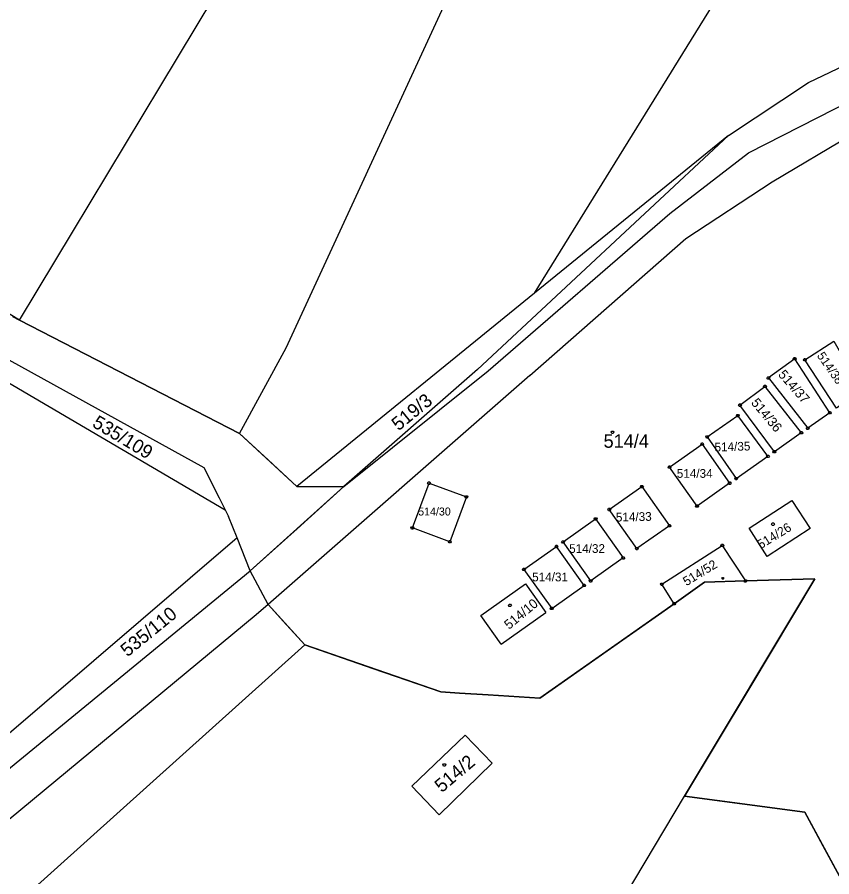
# Model space of a CAD drawing. Extents: x -634640 to -629202, y -1196156 to -1190068.
# Drawn here: x -632066.6 to -631964.4, y -1192921.2 to -1192813.3 of the extents above; entities that cross this region are included whole.
import ezdxf

# ---------------------------------------------------------------- set-up
doc = ezdxf.new("R2010")
doc.units = 0
for name, color, linetype in [('Obvod převzatý', 7, 'Continuous'), ('Obvod šetřený', 7, 'Continuous'), ('Vrstva 1', 7, 'Continuous'), ('Vrstva 2', 7, 'Continuous'), ('Vrstva 3', 7, 'Continuous'), ('Vrstva 5', 7, 'Continuous'), ('Vrstva 8', 7, 'Continuous')]:
    doc.layers.add(name, color=color, linetype=linetype)

msp = doc.modelspace()

# ---------------------------------------------------------------- linework, layer by layer
at = {"layer": 'Obvod převzatý'}
for points in [[(-632038.72, -1192865.56), (-632035.115, -1192868.88), (-632031.51, -1192872.2), (-632025.62, -1192872.23)], [(-632025.62, -1192872.23), (-632031.5, -1192877.515), (-632037.38, -1192882.8)], [(-632035.13, -1192887.03), (-632032.815, -1192889.565), (-632030.5, -1192892.1), (-632021.98, -1192895.05), (-632013.46, -1192898), (-632011.12, -1192898.15), (-632007.49, -1192898.38), (-632004.245, -1192898.59), (-632001, -1192898.8), (-631992.575, -1192892.865), (-631984.15, -1192886.93), (-631980.34, -1192884.24), (-631975.21, -1192884.08), (-631970.855, -1192883.94), (-631966.5, -1192883.8), (-631974.67, -1192897.455), (-631982.84, -1192911.11)]]:
    msp.add_lwpolyline(points, dxfattribs=at)
at = {"layer": 'Obvod šetřený'}
msp.add_line((-632035.13, -1192887.03), (-632037.38, -1192882.8), dxfattribs=at)
for points in [[(-632038.72, -1192865.56), (-632052.53, -1192858.45), (-632066.34, -1192851.34), (-632084.4, -1192840.38), (-632101.57, -1192829.88), (-632120.195, -1192818.495), (-632138.82, -1192807.11), (-632139.83, -1192806.49), (-632148.825, -1192801.24), (-632157.82, -1192795.99), (-632167.43, -1192790.385), (-632177.04, -1192784.78), (-632195.93, -1192773.755), (-632214.82, -1192762.73), (-632233.505, -1192751.82), (-632252.19, -1192740.91), (-632270.795, -1192730.055), (-632289.4, -1192719.2), (-632293.81, -1192716.63), (-632307.91, -1192708.405), (-632322.01, -1192700.18), (-632332.91, -1192693.815), (-632343.81, -1192687.45)], [(-631881.59, -1192883.11), (-631882.955, -1192885.455), (-631884.32, -1192887.8), (-631884.83, -1192886.64), (-631885.34, -1192885.48), (-631901.16, -1192887.14), (-631916.98, -1192888.8), (-631933.245, -1192909.24), (-631949.51, -1192929.68), (-631956.32, -1192925.645), (-631963.13, -1192921.61), (-631965.445, -1192917.355), (-631967.76, -1192913.1), (-631975.3, -1192912.105), (-631982.84, -1192911.11)]]:
    msp.add_lwpolyline(points, dxfattribs=at)
at = {"layer": 'Vrstva 1'}
for p, q in [((-632001.69, -1192847.96), (-631910.15, -1192700.05)), ((-632066.34, -1192851.34), (-631994.7, -1192732.44)), ((-632032.85, -1192854.81), (-631979.98, -1192740.13)), ((-631967.27, -1192821.5), (-631956.23, -1192816.21)), ((-631977.31, -1192828.14), (-631967.27, -1192821.5)), ((-631974.82, -1192830.35), (-631961.8, -1192823.68)), ((-632008.84, -1192857.55), (-631977.31, -1192828.14)), ((-631977.31, -1192828.14), (-632001.69, -1192847.96)), ((-631971.86, -1192833.96), (-631960.48, -1192827.21)), ((-631984.69, -1192837.97), (-631974.82, -1192830.35)), ((-631982.7, -1192841.11), (-631971.86, -1192833.96)), ((-632007.49, -1192857.7), (-631984.69, -1192837.97)), ((-632002.29, -1192858.29), (-631982.7, -1192841.11)), ((-632001.69, -1192847.96), (-632031.51, -1192872.2)), ((-632067.23, -1192850.88), (-632066.34, -1192851.34)), ((-632066.34, -1192851.34), (-632038.72, -1192865.56)), ((-632038.72, -1192865.56), (-632032.85, -1192854.81)), ((-632068.95, -1192855.67), (-632043.18, -1192869.83)), ((-631969.02, -1192856.18), (-631972.32, -1192858.6)), ((-631964.61, -1192862.96), (-631969.02, -1192856.18)), ((-632070.2, -1192857.75), (-632040.51, -1192875.14)), ((-632002.29, -1192858.29), (-632035.13, -1192887.03)), ((-632008.84, -1192857.55), (-632025.62, -1192872.23)), ((-632025.62, -1192872.23), (-632007.49, -1192857.7)), ((-631972.32, -1192858.6), (-631967.38, -1192864.91)), ((-631975.89, -1192862.01), (-631972.75, -1192859.65)), ((-631972.75, -1192859.65), (-631968.19, -1192865.48)), ((-631971.57, -1192867.85), (-631975.89, -1192862.01)), ((-631980, -1192866), (-631976.16, -1192863.32)), ((-631964.61, -1192862.96), (-631967.38, -1192864.91)), ((-632038.72, -1192865.56), (-632031.51, -1192872.2)), ((-631980, -1192866), (-631976.37, -1192871.23)), ((-631968.19, -1192865.48), (-631971.57, -1192867.85)), ((-631980.64, -1192866.9), (-631977.19, -1192871.8)), ((-632043.18, -1192869.83), (-632041.27, -1192873.63)), ((-632037.38, -1192882.8), (-632025.62, -1192872.23)), ((-632031.51, -1192872.2), (-632025.62, -1192872.23)), ((-632017.02, -1192877.42), (-632014.93, -1192871.8)), ((-632014.93, -1192871.8), (-632010.24, -1192873.53)), ((-631977.19, -1192871.8), (-631981.28, -1192874.68)), ((-632010.24, -1192873.53), (-632012.32, -1192879.16)), ((-632041.27, -1192873.63), (-632040.51, -1192875.14)), ((-632040.51, -1192875.14), (-632040.09, -1192875.97)), ((-632039.03, -1192878.65), (-632040.09, -1192875.97)), ((-632012.32, -1192879.16), (-632017.02, -1192877.42)), ((-631984.74, -1192877.14), (-631988.84, -1192880.01)), ((-632039.03, -1192878.65), (-632080.95, -1192914.66)), ((-632037.38, -1192882.8), (-632039.03, -1192878.65)), ((-632003.01, -1192882.62), (-631998.93, -1192879.75)), ((-631995.45, -1192884.64), (-631998.93, -1192879.75)), ((-631985.7, -1192884.5), (-631978.11, -1192879.62)), ((-631978.11, -1192879.62), (-631975.21, -1192884.08)), ((-632079.04, -1192916.97), (-632037.38, -1192882.8)), ((-632003.01, -1192882.62), (-631999.53, -1192887.52)), ((-631980.34, -1192884.24), (-631984.15, -1192886.93)), ((-631982.84, -1192911.11), (-631966.5, -1192883.8)), ((-631975.21, -1192884.08), (-631980.34, -1192884.24)), ((-631966.5, -1192883.8), (-631975.21, -1192884.08)), ((-632008.42, -1192888.41), (-632002.82, -1192884.43)), ((-632002.82, -1192884.43), (-632000.27, -1192888.02)), ((-631999.53, -1192887.52), (-631995.45, -1192884.64)), ((-631984.15, -1192886.93), (-631985.7, -1192884.5)), ((-632035.13, -1192887.03), (-632036.64, -1192888.35)), ((-632030.5, -1192892.1), (-632035.13, -1192887.03)), ((-631984.15, -1192886.93), (-632001, -1192898.8)), ((-632036.64, -1192888.35), (-632075.85, -1192920.82)), ((-632005.87, -1192892), (-632008.42, -1192888.41)), ((-632005.87, -1192892), (-632000.27, -1192888.02)), ((-632030.5, -1192892.1), (-632121.63, -1192973.87)), ((-632013.46, -1192898), (-632030.5, -1192892.1)), ((-632011.12, -1192898.15), (-632013.46, -1192898)), ((-632007.49, -1192898.38), (-632011.12, -1192898.15)), ((-632001, -1192898.8), (-632007.49, -1192898.38)), ((-632017.09, -1192909.84), (-632010.38, -1192903.45)), ((-632010.38, -1192903.45), (-632006.99, -1192906.95)), ((-632006.99, -1192906.95), (-632013.66, -1192913.42)), ((-632013.66, -1192913.42), (-632017.09, -1192909.84)), ((-632058.84, -1193038.11), (-631982.84, -1192911.11)), ((-631982.84, -1192911.11), (-631967.76, -1192913.1)), ((-631967.76, -1192913.1), (-631963.13, -1192921.61))]:
    msp.add_line(p, q, dxfattribs=at)
for points in [[(-631963.79, -1192862.39), (-631967.75, -1192856.31), (-631964.11, -1192853.98), (-631960.58, -1192860.14), (-631963.79, -1192862.39)], [(-631976.37, -1192871.23), (-631972.38, -1192868.43), (-631976.16, -1192863.32)], [(-631981.28, -1192874.68), (-631984.73, -1192869.78), (-631980.64, -1192866.9)], [(-631988.84, -1192880.01), (-631992.3, -1192875.11), (-631988.2, -1192872.24), (-631984.74, -1192877.14)], [(-631974.74, -1192877.44), (-631969.36, -1192873.98), (-631967.07, -1192877.49), (-631972.48, -1192881), (-631974.74, -1192877.44)], [(-631998.1, -1192879.18), (-631994.01, -1192876.29), (-631990.54, -1192881.19)], [(-631990.54, -1192881.19), (-631994.63, -1192884.07), (-631998.1, -1192879.18)]]:
    msp.add_lwpolyline(points, dxfattribs=at)
at = {"layer": 'Vrstva 3'}
for points in [[(-631991.8, -1192865.27), (-631991.71, -1192865.42), (-631991.8, -1192865.57), (-631991.98, -1192865.57), (-631992.07, -1192865.42), (-631991.98, -1192865.27), (-631991.8, -1192865.27)], [(-631977.98, -1192883.65), (-631977.919, -1192883.75), (-631977.98, -1192883.85), (-631978.1, -1192883.85), (-631978.161, -1192883.75), (-631978.1, -1192883.65), (-631977.98, -1192883.65)]]:
    msp.add_lwpolyline(points, dxfattribs=at)
at = {"layer": 'Vrstva 5'}
for points in [[(-631971.65, -1192876.8), (-631971.56, -1192876.95), (-631971.65, -1192877.1), (-631971.83, -1192877.1), (-631971.92, -1192876.95), (-631971.83, -1192876.8), (-631971.65, -1192876.8)], [(-632004.68, -1192886.99), (-632004.59, -1192887.14), (-632004.68, -1192887.29), (-632004.86, -1192887.29), (-632004.95, -1192887.14), (-632004.86, -1192886.99), (-632004.68, -1192886.99)], [(-632012.91, -1192907.03), (-632012.82, -1192907.18), (-632012.91, -1192907.33), (-632013.09, -1192907.33), (-632013.18, -1192907.18), (-632013.09, -1192907.03), (-632012.91, -1192907.03)]]:
    msp.add_lwpolyline(points, dxfattribs=at)
at = {"layer": 'Vrstva 8'}
for points in [[(-631968.93, -1192856.03), (-631968.84, -1192856.18), (-631968.93, -1192856.33), (-631969.11, -1192856.33), (-631969.2, -1192856.18), (-631969.11, -1192856.03), (-631968.93, -1192856.03)], [(-631967.66, -1192856.16), (-631967.57, -1192856.31), (-631967.66, -1192856.46), (-631967.84, -1192856.46), (-631967.93, -1192856.31), (-631967.84, -1192856.16), (-631967.66, -1192856.16)], [(-631972.23, -1192858.45), (-631972.14, -1192858.6), (-631972.23, -1192858.75), (-631972.41, -1192858.75), (-631972.5, -1192858.6), (-631972.41, -1192858.45), (-631972.23, -1192858.45)], [(-631972.66, -1192859.5), (-631972.57, -1192859.65), (-631972.66, -1192859.8), (-631972.84, -1192859.8), (-631972.93, -1192859.65), (-631972.84, -1192859.5), (-631972.66, -1192859.5)], [(-631975.8, -1192861.86), (-631975.71, -1192862.01), (-631975.8, -1192862.16), (-631975.98, -1192862.16), (-631976.07, -1192862.01), (-631975.98, -1192861.86), (-631975.8, -1192861.86)], [(-631976.07, -1192863.17), (-631975.98, -1192863.32), (-631976.07, -1192863.47), (-631976.25, -1192863.47), (-631976.34, -1192863.32), (-631976.25, -1192863.17), (-631976.07, -1192863.17)], [(-631964.52, -1192862.81), (-631964.43, -1192862.96), (-631964.52, -1192863.11), (-631964.7, -1192863.11), (-631964.79, -1192862.96), (-631964.7, -1192862.81), (-631964.52, -1192862.81)], [(-631967.29, -1192864.76), (-631967.2, -1192864.91), (-631967.29, -1192865.06), (-631967.47, -1192865.06), (-631967.56, -1192864.91), (-631967.47, -1192864.76), (-631967.29, -1192864.76)], [(-631979.91, -1192865.85), (-631979.82, -1192866), (-631979.91, -1192866.15), (-631980.09, -1192866.15), (-631980.18, -1192866), (-631980.09, -1192865.85), (-631979.91, -1192865.85)], [(-631968.1, -1192865.33), (-631968.01, -1192865.48), (-631968.1, -1192865.63), (-631968.28, -1192865.63), (-631968.37, -1192865.48), (-631968.28, -1192865.33), (-631968.1, -1192865.33)], [(-631980.55, -1192866.75), (-631980.46, -1192866.9), (-631980.55, -1192867.05), (-631980.73, -1192867.05), (-631980.82, -1192866.9), (-631980.73, -1192866.75), (-631980.55, -1192866.75)], [(-631971.48, -1192867.7), (-631971.39, -1192867.85), (-631971.48, -1192868), (-631971.66, -1192868), (-631971.75, -1192867.85), (-631971.66, -1192867.7), (-631971.48, -1192867.7)], [(-631972.29, -1192868.28), (-631972.2, -1192868.43), (-631972.29, -1192868.58), (-631972.47, -1192868.58), (-631972.56, -1192868.43), (-631972.47, -1192868.28), (-631972.29, -1192868.28)], [(-631984.64, -1192869.63), (-631984.55, -1192869.78), (-631984.64, -1192869.93), (-631984.82, -1192869.93), (-631984.91, -1192869.78), (-631984.82, -1192869.63), (-631984.64, -1192869.63)], [(-631976.28, -1192871.08), (-631976.19, -1192871.23), (-631976.28, -1192871.38), (-631976.46, -1192871.38), (-631976.55, -1192871.23), (-631976.46, -1192871.08), (-631976.28, -1192871.08)], [(-632014.84, -1192871.65), (-632014.75, -1192871.8), (-632014.84, -1192871.95), (-632015.02, -1192871.95), (-632015.11, -1192871.8), (-632015.02, -1192871.65), (-632014.84, -1192871.65)], [(-631988.11, -1192872.09), (-631988.02, -1192872.24), (-631988.11, -1192872.39), (-631988.29, -1192872.39), (-631988.38, -1192872.24), (-631988.29, -1192872.09), (-631988.11, -1192872.09)], [(-631977.1, -1192871.65), (-631977.01, -1192871.8), (-631977.1, -1192871.95), (-631977.28, -1192871.95), (-631977.37, -1192871.8), (-631977.28, -1192871.65), (-631977.1, -1192871.65)], [(-632010.15, -1192873.38), (-632010.06, -1192873.53), (-632010.15, -1192873.68), (-632010.33, -1192873.68), (-632010.42, -1192873.53), (-632010.33, -1192873.38), (-632010.15, -1192873.38)], [(-631981.19, -1192874.53), (-631981.1, -1192874.68), (-631981.19, -1192874.83), (-631981.37, -1192874.83), (-631981.46, -1192874.68), (-631981.37, -1192874.53), (-631981.19, -1192874.53)], [(-631992.21, -1192874.96), (-631992.12, -1192875.11), (-631992.21, -1192875.26), (-631992.39, -1192875.26), (-631992.48, -1192875.11), (-631992.39, -1192874.96), (-631992.21, -1192874.96)], [(-631993.92, -1192876.14), (-631993.83, -1192876.29), (-631993.92, -1192876.44), (-631994.1, -1192876.44), (-631994.19, -1192876.29), (-631994.1, -1192876.14), (-631993.92, -1192876.14)], [(-632016.93, -1192877.27), (-632016.84, -1192877.42), (-632016.93, -1192877.57), (-632017.11, -1192877.57), (-632017.2, -1192877.42), (-632017.11, -1192877.27), (-632016.93, -1192877.27)], [(-631984.65, -1192876.99), (-631984.56, -1192877.14), (-631984.65, -1192877.29), (-631984.83, -1192877.29), (-631984.92, -1192877.14), (-631984.83, -1192876.99), (-631984.65, -1192876.99)], [(-632012.23, -1192879.01), (-632012.14, -1192879.16), (-632012.23, -1192879.31), (-632012.41, -1192879.31), (-632012.5, -1192879.16), (-632012.41, -1192879.01), (-632012.23, -1192879.01)], [(-631998.84, -1192879.6), (-631998.75, -1192879.75), (-631998.84, -1192879.9), (-631999.02, -1192879.9), (-631999.11, -1192879.75), (-631999.02, -1192879.6), (-631998.84, -1192879.6)], [(-631998.01, -1192879.03), (-631997.92, -1192879.18), (-631998.01, -1192879.33), (-631998.19, -1192879.33), (-631998.28, -1192879.18), (-631998.19, -1192879.03), (-631998.01, -1192879.03)], [(-631988.75, -1192879.86), (-631988.66, -1192880.01), (-631988.75, -1192880.16), (-631988.93, -1192880.16), (-631989.02, -1192880.01), (-631988.93, -1192879.86), (-631988.75, -1192879.86)], [(-631978.02, -1192879.47), (-631977.93, -1192879.62), (-631978.02, -1192879.77), (-631978.2, -1192879.77), (-631978.29, -1192879.62), (-631978.2, -1192879.47), (-631978.02, -1192879.47)], [(-631990.45, -1192881.04), (-631990.36, -1192881.19), (-631990.45, -1192881.34), (-631990.63, -1192881.34), (-631990.72, -1192881.19), (-631990.63, -1192881.04), (-631990.45, -1192881.04)], [(-632002.92, -1192882.47), (-632002.83, -1192882.62), (-632002.92, -1192882.77), (-632003.1, -1192882.77), (-632003.19, -1192882.62), (-632003.1, -1192882.47), (-632002.92, -1192882.47)], [(-631994.54, -1192883.92), (-631994.45, -1192884.07), (-631994.54, -1192884.22), (-631994.72, -1192884.22), (-631994.81, -1192884.07), (-631994.72, -1192883.92), (-631994.54, -1192883.92)], [(-631985.61, -1192884.35), (-631985.52, -1192884.5), (-631985.61, -1192884.65), (-631985.79, -1192884.65), (-631985.88, -1192884.5), (-631985.79, -1192884.35), (-631985.61, -1192884.35)], [(-631975.12, -1192883.93), (-631975.03, -1192884.08), (-631975.12, -1192884.23), (-631975.3, -1192884.23), (-631975.39, -1192884.08), (-631975.3, -1192883.93), (-631975.12, -1192883.93)], [(-631995.36, -1192884.49), (-631995.27, -1192884.64), (-631995.36, -1192884.79), (-631995.54, -1192884.79), (-631995.63, -1192884.64), (-631995.54, -1192884.49), (-631995.36, -1192884.49)], [(-631999.44, -1192887.37), (-631999.35, -1192887.52), (-631999.44, -1192887.67), (-631999.62, -1192887.67), (-631999.71, -1192887.52), (-631999.62, -1192887.37), (-631999.44, -1192887.37)], [(-631984.06, -1192886.78), (-631983.97, -1192886.93), (-631984.06, -1192887.08), (-631984.24, -1192887.08), (-631984.33, -1192886.93), (-631984.24, -1192886.78), (-631984.06, -1192886.78)]]:
    msp.add_lwpolyline(points, dxfattribs=at)

# ---------------------------------------------------------------- texts
at = {"layer": 'Vrstva 2'}
for s, height, rotation, p in [('514/38', 1.1, 304.98543, (-631966.274, -1192855.811)), ('514/37', 1.2, 311.11608, (-631971.17, -1192858.22)), ('519/3', 1.7, 39.07572, (-632018.766, -1192865.31)), ('514/36', 1.2, 309.91287, (-631974.568, -1192861.753)), ('535/109', 1.7, 329.16425, (-632057.326, -1192864.642)), ('514/35', 1.1, 2.00535, (-631979.065, -1192867.84)), ('514/33', 1.1, 1.3751, (-631991.456, -1192876.629)), ('514/26', 1.14, 31.51268, (-631973.29, -1192880.109)), ('514/52', 1.14, 31.39809, (-631982.609, -1192884.744)), ('514/10', 1.19, 39.59138, (-632004.882, -1192890.224)), ('535/110', 1.7, 39.07572, (-632052.796, -1192893.68)), ('514/2', 1.7, 40.22164, (-632013.329, -1192910.727))]:
    msp.add_text(s, height=height, rotation=rotation, dxfattribs=at).set_placement(p)
for s, height, p in [('514/4', 1.7, (-631993.013, -1192867.36)), ('514/34', 1.1, (-631983.823, -1192871.13)), ('514/30', 1, (-632016.292, -1192875.86)), ('514/32', 1.1, (-631997.337, -1192880.56)), ('514/31', 1.1, (-632001.979, -1192884.13))]:
    msp.add_text(s, height=height, dxfattribs=at).set_placement(p)

doc.saveas('drawing.dxf')
